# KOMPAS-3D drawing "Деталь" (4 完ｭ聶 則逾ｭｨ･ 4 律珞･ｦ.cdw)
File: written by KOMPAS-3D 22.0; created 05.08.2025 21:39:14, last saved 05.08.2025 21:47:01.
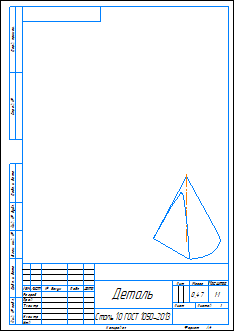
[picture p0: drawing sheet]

Sheet 1: A4, portrait

Document properties: Автор: user; Масса: 0.468006; Полное имя файла: G:\08 05 вторник\2025 НГ Лаб работы\Лаб 4 Сечение конуса\4 Чертежи\4 Конус Сечение 4 Чертеж.cdw

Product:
- Part/product: Деталь
    Масса: 0.468006

Title block, sheet 1: Наименование: Деталь; Материал: Сталь 10 ГОСТ 1050-2013; Масса: 0,47; Количество листов документа: 1; Форматы листов документа: A4; stored path: G:\08 05 вторник\2025 НГ Лаб работы\Лаб 4 Сечение конуса\4 Чертежи\4 Конус Сечение 6 Чертеж.cdw

Views: Изометрия 2
Dimensions and other numbers on the sheet: 1:1; 1; 0,47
